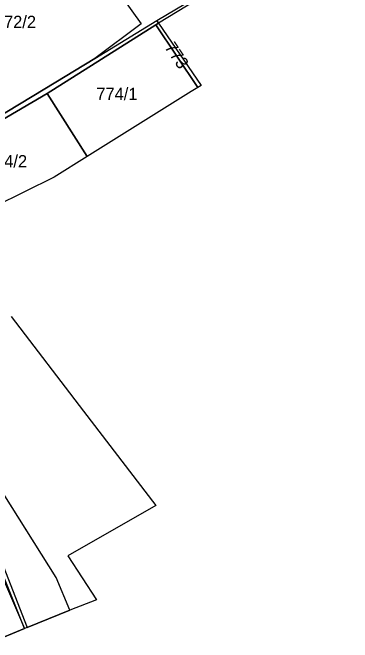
# Model space of a CAD drawing. Extents: x -623250 to -619626, y -1079612 to -1075424.
# Drawn here: x -620489 to -620213, y -1077808 to -1077297 of the extents above; entities that cross this region are included whole.
import ezdxf

# ---------------------------------------------------------------- set-up
doc = ezdxf.new("R2010")
doc.units = 0
for name, color, linetype in [('Hranice převzatá (KoPÚ Hrušová)', 7, 'Continuous'), ('Katastrální hranice', 7, 'Continuous'), ('Parcela nároku', 7, 'Continuous'), ('Parcelní číslo', 7, 'Continuous'), ('Vodní toky', 7, 'Continuous')]:
    doc.layers.add(name, color=color, linetype=linetype)

msp = doc.modelspace()

# ---------------------------------------------------------------- linework, layer by layer
at = {"layer": 'Hranice převzatá (KoPÚ Hrušová)'}
for points in [[(-620308.56, -1077267.13), (-620370.5, -1077305.13), (-620335.81, -1077355.75), (-620338.7, -1077357.55), (-620343.94, -1077360.82), (-620428.6, -1077413.64), (-620455.44, -1077430.38), (-620528, -1077466.25)], [(-620490.13, -1077543.5), (-620431.47, -1077620.42), (-620372.81, -1077697.34), (-620444.1, -1077738.11), (-620420.92, -1077773.91), (-620442.63, -1077782.38), (-620477.3, -1077796.45), (-620479.44, -1077797.32), (-620507, -1077808.5)]]:
    msp.add_lwpolyline(points, dxfattribs=at)
at = {"layer": 'Katastrální hranice'}
for p, q in [((-620453.81, -1077755.63), (-620553.25, -1077597.63)), ((-620442.63, -1077782.38), (-620453.81, -1077755.63))]:
    msp.add_line(p, q, dxfattribs=at)
at = {"layer": 'Parcela nároku'}
for points in [[(-620213.7, -1077201.11), (-620245.94, -1077139.65), (-620275.1, -1077087.21), (-620337.73, -1077128.15), (-620456.45, -1077205.38), (-620384.64, -1077305.72), (-620422.26, -1077333.77), (-620371.95, -1077302.9), (-620309.42, -1077265.74)], [(-620213.7, -1077201.11), (-620213.25, -1077201.98), (-620212.99, -1077202.5), (-620227.43, -1077212.27), (-620308.56, -1077267.13), (-620370.5, -1077305.13), (-620371.95, -1077302.9), (-620309.42, -1077265.74)], [(-620456.45, -1077205.38), (-620384.64, -1077305.72), (-620422.26, -1077333.77), (-620462.8, -1077358.64), (-620524.9, -1077396.04), (-620539.81, -1077402.16), (-620543.64, -1077394.52), (-620559.44, -1077321.56), (-620568.57, -1077271.31)], [(-620422.26, -1077333.77), (-620371.95, -1077302.9), (-620370.5, -1077305.13), (-620372.79, -1077306.58), (-620460.93, -1077362.28), (-620523.52, -1077399.04), (-620547.34, -1077409.36), (-620563.83, -1077412.93), (-620594.08, -1077416.27), (-620652.47, -1077416.15), (-620697.72, -1077411.88), (-620745.96, -1077407.32), (-620784.54, -1077405.49), (-620787.68, -1077402.01), (-620746, -1077403.66), (-620703.91, -1077407.59), (-620652.15, -1077412.42), (-620593.85, -1077412.5), (-620564.2, -1077409.47), (-620545.47, -1077403.86), (-620539.81, -1077402.16), (-620524.9, -1077396.04), (-620462.8, -1077358.64)], [(-620338.7, -1077357.55), (-620343.94, -1077360.82), (-620428.6, -1077413.64), (-620460.93, -1077362.28), (-620372.79, -1077306.58)], [(-620335.81, -1077355.75), (-620338.7, -1077357.55), (-620372.79, -1077306.58), (-620370.5, -1077305.13)], [(-620460.93, -1077362.28), (-620428.6, -1077413.64), (-620455.44, -1077430.38), (-620528, -1077466.25), (-620533.24, -1077454.08), (-620541.8, -1077430.35), (-620547.34, -1077409.36), (-620523.52, -1077399.04)], [(-620718.81, -1077682.81), (-620800.08, -1077592.94), (-620851.45, -1077542.42), (-620845.11, -1077577.39), (-620844.37, -1077593.81), (-620834.66, -1077602.26), (-620822.67, -1077642.69), (-620798.58, -1077671.35), (-620743.55, -1077716.58), (-620685.44, -1077756.32), (-620662.26, -1077773.11), (-620654.94, -1077775.38), (-620619.25, -1077805.5), (-620545.44, -1077749.25), (-620507, -1077808.5), (-620479.44, -1077797.32), (-620501.31, -1077742.94), (-620532.98, -1077681.37), (-620584.3, -1077610.83), (-620597.88, -1077593.11), (-620611.54, -1077603.19), (-620646.97, -1077626.81), (-620682.61, -1077652.52)], [(-620530.46, -1077679.74), (-620498.61, -1077741.4), (-620477.3, -1077796.45), (-620479.44, -1077797.32), (-620501.31, -1077742.94), (-620532.98, -1077681.37), (-620584.3, -1077610.83), (-620597.88, -1077593.11), (-620599.32, -1077591.23), (-620596.08, -1077590.97)], [(-620553.25, -1077597.63), (-620557.23, -1077593.02), (-620596.08, -1077590.97), (-620530.46, -1077679.74), (-620498.61, -1077741.4), (-620477.3, -1077796.45), (-620442.63, -1077782.38), (-620453.81, -1077755.63)]]:
    msp.add_lwpolyline(points, close=True, dxfattribs=at)
at = {"layer": 'Vodní toky'}
msp.add_line((-620505.28, -1077737.08), (-620479.44, -1077797.32), dxfattribs=at)

# ---------------------------------------------------------------- texts
at = {"layer": 'Parcelní číslo'}
for s, p in [('772/2', (-620503.51, -1077309.14)), ('774/1', (-620421.09, -1077367.71)), ('774/2', (-620510.76, -1077422.41))]:
    msp.add_text(s, height=10, dxfattribs=at).set_placement(p)
msp.add_text('773', height=10, rotation=303.7449, dxfattribs=at).set_placement((-620366.02, -1077324.77))

doc.saveas('drawing.dxf')
